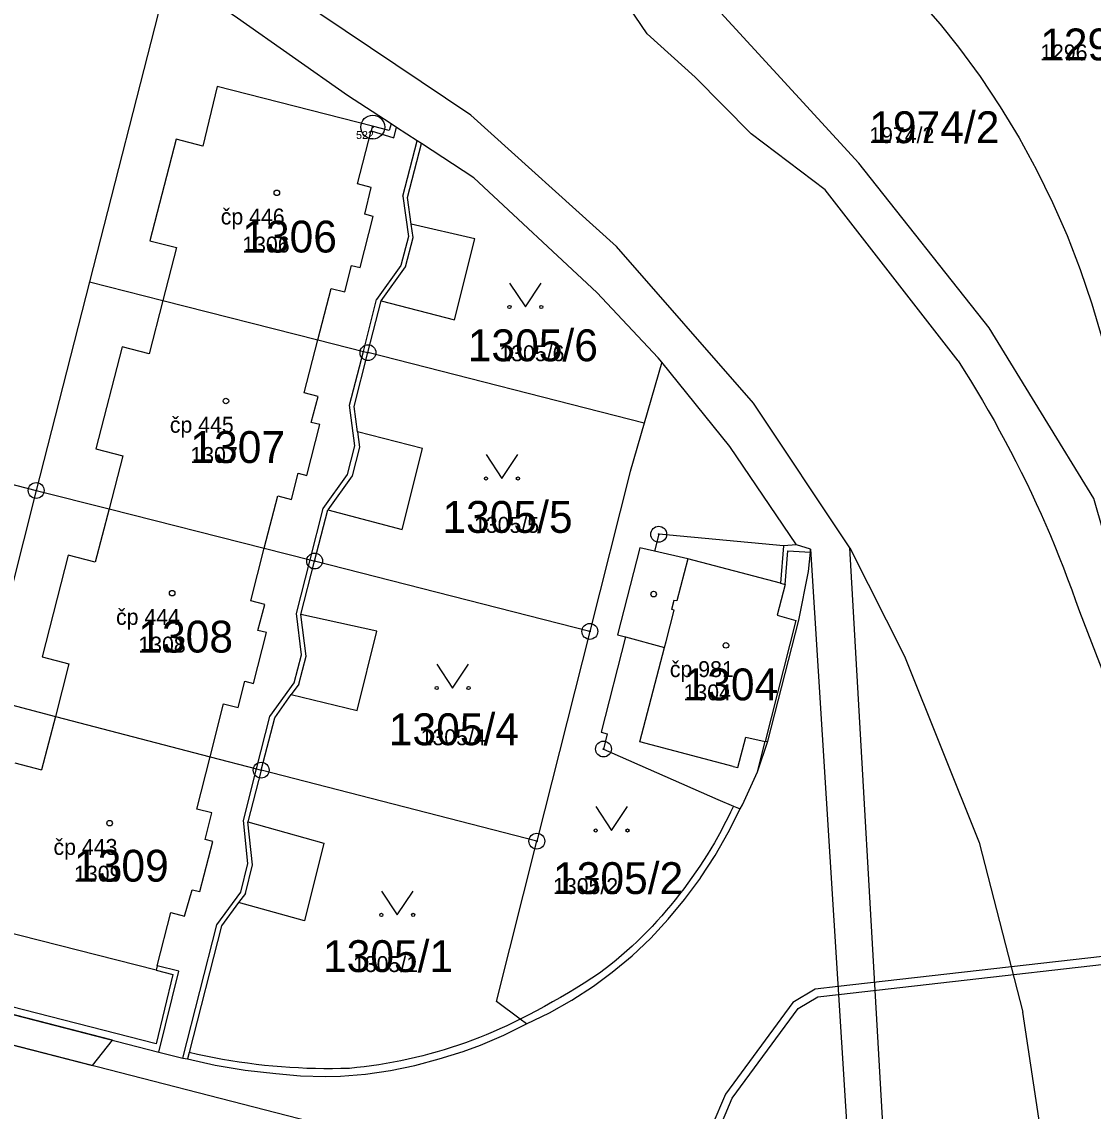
# Model space of a CAD drawing. Extents: x -763628 to -761565, y -976033 to -973833.
# Drawn here: x -762263.5 to -762196.1, y -975446.4 to -975378 of the extents above; entities that cross this region are included whole.
import ezdxf

# ---------------------------------------------------------------- set-up
doc = ezdxf.new("R2010")
doc.units = 0
for name, color, linetype in [('KN_cisla parcel 1000', 7, 'Continuous'), ('KN_cisla parcel 500', 7, 'Continuous'), ('KN_cisla popisna 500', 7, 'Continuous'), ('KN_hranice parcel', 7, 'Continuous'), ('KN_vecna bremena', 7, 'Continuous'), ('KN_vnitrni kresba parcel', 7, 'Continuous'), ('KN_znacky bodu BP', 7, 'Continuous'), ('KN_znacky budov', 7, 'Continuous'), ('KN_znacky kultur', 7, 'Continuous')]:
    doc.layers.add(name, color=color, linetype=linetype)

msp = doc.modelspace()

# ---------------------------------------------------------------- linework, layer by layer
at = {"layer": 'KN_hranice parcel'}
for p, q in [((-762259.22, -975394.29), (-762262.57, -975407.4)), ((-762224.37, -975403.18), (-762241.72, -975398.74)), ((-762223.26, -975399.34), (-762224.37, -975403.18)), ((-762283.84, -975401.95), (-762262.57, -975407.4)), ((-762262.57, -975407.4), (-762265.89, -975420.41)), ((-762213.91, -975411.08), (-762214.79, -975410.81)), ((-762227.78, -975416.25), (-762245.07, -975411.83)), ((-762227.78, -975416.25), (-762231.11, -975429.43)), ((-762231.11, -975429.43), (-762248.43, -975424.97))]:
    msp.add_line(p, q, dxfattribs=at)
for points in [[(-762225.71, -975363.26), (-762223.626, -975364.193), (-762221.585, -975365.216), (-762219.591, -975366.327), (-762217.647, -975367.525), (-762215.758, -975368.807), (-762213.926, -975370.17), (-762212.156, -975371.612), (-762210.451, -975373.131), (-762208.814, -975374.722), (-762207.248, -975376.384), (-762205.756, -975378.112), (-762204.607, -975379.556), (-762203.257, -975381.398), (-762201.989, -975383.296), (-762200.805, -975385.248), (-762199.708, -975387.251), (-762198.699, -975389.299), (-762197.781, -975391.39), (-762196.956, -975393.518), (-762196.224, -975395.681), (-762195.588, -975397.874)], [(-762193.77, -975416.03), (-762194.29, -975414.25), (-762196.11, -975407.9), (-762202.69, -975397.18), (-762210.87, -975386.84), (-762225.62, -975370.76), (-762226.44, -975366.62)], [(-762254.57, -975376.08), (-762254.68, -975376.52), (-762259.22, -975394.29)], [(-762238.36, -975385.61), (-762238.63, -975385.43), (-762239.93, -975384.59), (-762240.26, -975384.37), (-762243, -975382.59), (-762249.92, -975377.74), (-762250.92, -975377.04), (-762254.57, -975376.08)], [(-762241.72, -975398.74), (-762240.89, -975395.49), (-762236.28, -975396.68), (-762235.01, -975391.6), (-762239, -975390.68), (-762239.23, -975389), (-762238.36, -975385.61)], [(-762223.26, -975399.34), (-762223.48, -975399.07), (-762227.34, -975394.96), (-762235.07, -975387.76), (-762238.36, -975385.61)], [(-762259.22, -975394.29), (-762254.61, -975395.46), (-762244.88, -975397.94), (-762242.01, -975398.67), (-762241.72, -975398.74)], [(-762245.07, -975411.83), (-762244.24, -975408.61), (-762239.57, -975409.85), (-762238.3, -975404.77), (-762242.38, -975403.72), (-762242.59, -975402.12), (-762241.72, -975398.74)], [(-762214.79, -975410.81), (-762218.97, -975404.64), (-762223.26, -975399.34)], [(-762224.37, -975403.18), (-762225.25, -975406.21), (-762227.78, -975416.25)], [(-762262.57, -975407.4), (-762257.99, -975408.56), (-762248.24, -975411.03), (-762245.36, -975411.76), (-762245.07, -975411.83)], [(-762214.79, -975410.81), (-762215.61, -975410.87), (-762223.45, -975410.15), (-762223.72, -975411.21), (-762224.63, -975411.01), (-762226.05, -975416.46), (-762225.53, -975416.6), (-762227.07, -975422.58), (-762226.68, -975422.68), (-762226.92, -975423.64), (-762219.74, -975426.81), (-762218.76, -975427.22), (-762218.34, -975427.39)], [(-762218.34, -975427.39), (-762218.18, -975427.14), (-762217.25, -975425.08), (-762216.6, -975423.15), (-762214.65, -975415.55), (-762214.04, -975412.48), (-762213.92, -975411.27), (-762213.91, -975411.08)], [(-762213.91, -975411.08), (-762211.23, -975453.74), (-762211.16, -975455.66), (-762210.96, -975461.11), (-762210.75, -975466.8)], [(-762248.43, -975424.97), (-762247.58, -975421.68), (-762246.54, -975420.22), (-762242.4, -975421.21), (-762241.16, -975416.24), (-762245.93, -975415.19), (-762245.07, -975411.83)], [(-762265.89, -975420.41), (-762261.36, -975421.59), (-762251.64, -975424.13), (-762248.72, -975424.89), (-762248.43, -975424.97)], [(-762248.43, -975424.97), (-762249.26, -975428.21), (-762244.49, -975429.55), (-762245.71, -975434.44), (-762249.85, -975433.29), (-762250.93, -975434.75), (-762252.96, -975442.7), (-762253.06, -975443.11)], [(-762231.76, -975440.91), (-762230.308, -975440.204), (-762228.902, -975439.408), (-762227.548, -975438.528), (-762226.367, -975437.657), (-762225.127, -975436.623), (-762223.952, -975435.515), (-762222.849, -975434.335), (-762221.82, -975433.09), (-762220.825, -975431.748), (-762220.818, -975431.739), (-762219.906, -975430.339), (-762219.079, -975428.888), (-762218.34, -975427.39)], [(-762231.76, -975440.91), (-762232.16, -975440.61), (-762233.65, -975439.49), (-762231.11, -975429.43)], [(-762270.55, -975438.65), (-762254.86, -975442.68), (-762253.36, -975443.06), (-762253.06, -975443.11)], [(-762253.06, -975443.11), (-762251.328, -975443.491), (-762249.431, -975443.81), (-762247.52, -975444.03), (-762245.952, -975444.168), (-762244.379, -975444.206), (-762243.436, -975444.18), (-762241.866, -975444.058), (-762240.308, -975443.837), (-762238.767, -975443.517), (-762237.25, -975443.1), (-762235.729, -975442.64), (-762234.642, -975442.246), (-762233.18, -975441.623), (-762231.76, -975440.91)]]:
    msp.add_lwpolyline(points, dxfattribs=at)
at = {"layer": 'KN_vecna bremena'}
msp.add_lwpolyline([(-762318.38, -975428.27), (-762259.04, -975443.52), (-762257.78, -975441.93), (-762270.55, -975438.65), (-762291.9, -975433.17), (-762292.19, -975433.1), (-762293.64, -975432.73), (-762309.19, -975428.74)], dxfattribs=at)
msp.add_lwpolyline([(-762222.94, -975461.28), (-762220.48, -975449.5), (-762218.83, -975445.58), (-762214.68, -975439.95), (-762213.46, -975439.21), (-762212.15, -975439.06), (-762187.54, -975436.26), (-762187.63, -975435.77), (-762212.18, -975438.56), (-762213.62, -975438.72), (-762215.02, -975439.57), (-762219.26, -975445.33), (-762220.96, -975449.34), (-762223.45, -975461.3), (-762222.83, -975463.59), (-762222.27, -975463.74)], close=True, dxfattribs=at)
at = {"layer": 'KN_vnitrni kresba parcel'}
for p, q in [((-762224.17, -975378.71), (-762227.51, -975373.8)), ((-762235.26, -975383.83), (-762247.22, -975375.79)), ((-762221.15, -975381.43), (-762224.17, -975378.71)), ((-762217.64, -975385), (-762221.15, -975381.43)), ((-762251.2, -975382.03), (-762252.1, -975385.76)), ((-762241.44, -975384.52), (-762251.2, -975382.03)), ((-762226.11, -975392.08), (-762235.26, -975383.83)), ((-762242.37, -975388.14), (-762241.52, -975384.81)), ((-762241.44, -975384.52), (-762241.52, -975384.81)), ((-762241.52, -975384.81), (-762240.1, -975385.25)), ((-762240.38, -975384.79), (-762241.44, -975384.52)), ((-762240.26, -975384.37), (-762240.38, -975384.79)), ((-762240.1, -975385.25), (-762239.93, -975384.59)), ((-762253.78, -975385.32), (-762255.43, -975391.71)), ((-762252.1, -975385.76), (-762253.78, -975385.32)), ((-762239.52, -975388.92), (-762238.63, -975385.43)), ((-762212.99, -975388.51), (-762217.64, -975385)), ((-762241.51, -975388.37), (-762242.37, -975388.14)), ((-762241.92, -975390.05), (-762241.51, -975388.37)), ((-762239.52, -975388.92), (-762239.18, -975391.44)), ((-762204.64, -975399.25), (-762212.99, -975388.51)), ((-762242.21, -975393.4), (-762241.39, -975390.19)), ((-762241.39, -975390.19), (-762241.92, -975390.05)), ((-762238.89, -975391.51), (-762239, -975390.68)), ((-762255.43, -975391.71), (-762253.75, -975392.14)), ((-762239.18, -975391.44), (-762239.66, -975393.27)), ((-762239.36, -975393.35), (-762238.89, -975391.51)), ((-762253.75, -975392.14), (-762254.61, -975395.46)), ((-762217.49, -975401.91), (-762226.11, -975392.08)), ((-762243.18, -975394.93), (-762242.75, -975393.26)), ((-762242.75, -975393.26), (-762242.21, -975393.4)), ((-762239.66, -975393.27), (-762241.18, -975395.41)), ((-762240.89, -975395.49), (-762239.36, -975393.35)), ((-762244.88, -975397.94), (-762244.04, -975394.71)), ((-762244.04, -975394.71), (-762243.18, -975394.93)), ((-762254.61, -975395.46), (-762255.47, -975398.82)), ((-762242.01, -975398.67), (-762241.18, -975395.41)), ((-762245.73, -975401.27), (-762244.88, -975397.94)), ((-762257.16, -975398.38), (-762258.82, -975404.78)), ((-762255.47, -975398.82), (-762257.16, -975398.38)), ((-762242.88, -975402.04), (-762242.01, -975398.67)), ((-762244.86, -975401.49), (-762245.73, -975401.27)), ((-762245.28, -975403.13), (-762244.86, -975401.49)), ((-762242.55, -975404.6), (-762242.88, -975402.04)), ((-762211.43, -975411.01), (-762217.49, -975401.91)), ((-762245.56, -975406.45), (-762244.75, -975403.26)), ((-762244.75, -975403.26), (-762245.28, -975403.13)), ((-762242.38, -975403.72), (-762242.26, -975404.68)), ((-762258.82, -975404.78), (-762257.12, -975405.22)), ((-762243.01, -975406.39), (-762242.55, -975404.6)), ((-762242.26, -975404.68), (-762242.72, -975406.47)), ((-762257.12, -975405.22), (-762257.99, -975408.56)), ((-762246.52, -975407.96), (-762246.1, -975406.31)), ((-762246.1, -975406.31), (-762245.56, -975406.45)), ((-762244.54, -975408.53), (-762243.01, -975406.39)), ((-762242.72, -975406.47), (-762244.24, -975408.61)), ((-762248.24, -975411.03), (-762247.39, -975407.74)), ((-762247.39, -975407.74), (-762246.52, -975407.96)), ((-762257.99, -975408.56), (-762258.86, -975411.91)), ((-762245.36, -975411.76), (-762244.54, -975408.53)), ((-762215.61, -975410.87), (-762215.79, -975413.22)), ((-762260.55, -975411.47), (-762262.2, -975417.84)), ((-762258.86, -975411.91), (-762260.55, -975411.47)), ((-762249.09, -975414.33), (-762248.24, -975411.03)), ((-762221.62, -975411.69), (-762223.72, -975411.21)), ((-762215.5, -975413.3), (-762215.34, -975411.2)), ((-762215.34, -975411.2), (-762213.92, -975411.27)), ((-762209, -975453.44), (-762211.43, -975411.01)), ((-762211.43, -975411.01), (-762208, -975417.8)), ((-762246.22, -975415.12), (-762245.36, -975411.76)), ((-762221.62, -975411.69), (-762222.32, -975414.34)), ((-762215.79, -975413.22), (-762221.62, -975411.69)), ((-762215.5, -975413.3), (-762216, -975415.24)), ((-762215.79, -975413.22), (-762215.5, -975413.3)), ((-762248.21, -975414.56), (-762249.09, -975414.33)), ((-762222.49, -975414.3), (-762222.64, -975414.88)), ((-762222.32, -975414.34), (-762222.49, -975414.3)), ((-762248.64, -975416.19), (-762248.21, -975414.56)), ((-762222.98, -975416.89), (-762222.47, -975414.92)), ((-762222.47, -975414.92), (-762222.64, -975414.88)), ((-762197.01, -975415.01), (-762193.8, -975423.3)), ((-762245.9, -975417.72), (-762246.22, -975415.12)), ((-762245.61, -975417.8), (-762245.93, -975415.19)), ((-762214.83, -975415.57), (-762216.76, -975423.16)), ((-762216, -975415.24), (-762214.83, -975415.57)), ((-762248.92, -975419.52), (-762248.1, -975416.33)), ((-762248.1, -975416.33), (-762248.64, -975416.19)), ((-762225.53, -975416.6), (-762223.08, -975417.26)), ((-762223.08, -975417.26), (-762222.98, -975416.89)), ((-762246.35, -975419.48), (-762245.9, -975417.72)), ((-762246.06, -975419.56), (-762245.61, -975417.8)), ((-762224.64, -975423.19), (-762223.08, -975417.26)), ((-762208, -975417.8), (-762203.31, -975429.52)), ((-762262.2, -975417.84), (-762260.51, -975418.28)), ((-762260.51, -975418.28), (-762261.36, -975421.59)), ((-762249.88, -975421.04), (-762249.45, -975419.38)), ((-762249.45, -975419.38), (-762248.92, -975419.52)), ((-762247.88, -975421.6), (-762246.35, -975419.48)), ((-762246.06, -975419.56), (-762246.54, -975420.22)), ((-762251.64, -975424.13), (-762250.79, -975420.8)), ((-762250.79, -975420.8), (-762249.88, -975421.04)), ((-762261.36, -975421.59), (-762262.23, -975424.94)), ((-762248.72, -975424.89), (-762247.88, -975421.6)), ((-762218.77, -975424.74), (-762224.64, -975423.19)), ((-762218.47, -975424.81), (-762217.97, -975422.89)), ((-762217.97, -975422.89), (-762216.76, -975423.16)), ((-762217.25, -975425.08), (-762216.76, -975423.16)), ((-762216.76, -975423.16), (-762216.6, -975423.15)), ((-762263.92, -975424.5), (-762262.23, -975424.94)), ((-762252.48, -975427.41), (-762251.64, -975424.13)), ((-762249.55, -975428.14), (-762248.72, -975424.89)), ((-762218.77, -975424.74), (-762218.47, -975424.81)), ((-762251.53, -975427.65), (-762252.48, -975427.41)), ((-762251.95, -975429.32), (-762251.53, -975427.65)), ((-762211.66, -975455.7), (-762318.38, -975428.27)), ((-762249.26, -975430.84), (-762249.55, -975428.14)), ((-762248.97, -975430.92), (-762249.26, -975428.21)), ((-762252.28, -975432.6), (-762251.47, -975429.44)), ((-762251.47, -975429.44), (-762251.95, -975429.32)), ((-762203.31, -975429.52), (-762200.56, -975440.18)), ((-762249.72, -975432.63), (-762249.26, -975430.84)), ((-762249.42, -975432.71), (-762248.97, -975430.92)), ((-762253.24, -975434.13), (-762252.76, -975432.48)), ((-762252.76, -975432.48), (-762252.28, -975432.6)), ((-762251.22, -975434.68), (-762249.72, -975432.63)), ((-762249.42, -975432.71), (-762249.85, -975433.29)), ((-762254.96, -975437.25), (-762254.11, -975433.9)), ((-762254.11, -975433.9), (-762253.24, -975434.13)), ((-762253.36, -975443.06), (-762251.22, -975434.68)), ((-762255.04, -975437.54), (-762264.83, -975435.03)), ((-762254.96, -975437.25), (-762255.04, -975437.54)), ((-762255.04, -975437.54), (-762253.98, -975437.81)), ((-762253.6, -975437.6), (-762254.96, -975437.25)), ((-762254.86, -975442.68), (-762253.6, -975437.6)), ((-762255.04, -975442.16), (-762270.44, -975438.21)), ((-762253.98, -975437.81), (-762255.04, -975442.16)), ((-762198.91, -975451.2), (-762200.56, -975440.18))]:
    msp.add_line(p, q, dxfattribs=at)
for points in [[(-762204.64, -975399.25), (-762204.247, -975399.867), (-762203.861, -975400.488), (-762203.481, -975401.113), (-762203.107, -975401.741), (-762202.74, -975402.374), (-762202.379, -975403.01), (-762202.024, -975403.649), (-762201.676, -975404.293), (-762201.334, -975404.939), (-762200.999, -975405.589), (-762200.67, -975406.243), (-762200.348, -975406.899), (-762200.033, -975407.559), (-762199.724, -975408.222), (-762199.422, -975408.888), (-762199.127, -975409.557), (-762198.838, -975410.229), (-762198.557, -975410.904), (-762198.282, -975411.582), (-762198.014, -975412.262), (-762197.752, -975412.945), (-762197.498, -975413.631), (-762197.25, -975414.319), (-762197.01, -975415.01)], [(-762218.76, -975427.22), (-762218.943, -975427.613), (-762219.132, -975428.004), (-762219.327, -975428.391), (-762219.529, -975428.775), (-762219.736, -975429.156), (-762219.95, -975429.533), (-762220.17, -975429.907), (-762220.396, -975430.277), (-762220.628, -975430.643), (-762220.866, -975431.006), (-762221.109, -975431.365), (-762221.358, -975431.72), (-762221.613, -975432.071), (-762221.874, -975432.418), (-762222.14, -975432.76)], [(-762222.14, -975432.76), (-762222.412, -975433.11), (-762222.69, -975433.455), (-762222.974, -975433.794), (-762223.264, -975434.129), (-762223.56, -975434.459), (-762223.861, -975434.784), (-762224.168, -975435.103), (-762224.481, -975435.417), (-762224.799, -975435.725), (-762225.122, -975436.027), (-762225.451, -975436.324), (-762225.785, -975436.615), (-762226.124, -975436.901), (-762226.468, -975437.18), (-762226.817, -975437.453), (-762227.17, -975437.72)], [(-762227.17, -975437.72), (-762227.652, -975438.037), (-762228.138, -975438.348), (-762228.629, -975438.652), (-762229.122, -975438.951), (-762229.62, -975439.243), (-762230.121, -975439.529), (-762230.626, -975439.809), (-762231.134, -975440.082), (-762231.645, -975440.349), (-762232.16, -975440.61)], [(-762232.16, -975440.61), (-762232.579, -975440.819), (-762233.001, -975441.021), (-762233.426, -975441.217), (-762233.854, -975441.406), (-762234.286, -975441.588), (-762234.72, -975441.763), (-762235.156, -975441.932), (-762235.596, -975442.093), (-762236.038, -975442.247), (-762236.482, -975442.394), (-762236.929, -975442.535), (-762237.377, -975442.668), (-762237.828, -975442.794), (-762238.281, -975442.912), (-762238.735, -975443.024), (-762239.192, -975443.128), (-762239.65, -975443.225), (-762240.109, -975443.315), (-762240.57, -975443.398), (-762241.032, -975443.473), (-762241.495, -975443.541), (-762241.959, -975443.601), (-762242.424, -975443.654), (-762242.89, -975443.7)], [(-762242.89, -975443.7), (-762243.424, -975443.715), (-762243.958, -975443.722), (-762244.492, -975443.722), (-762245.026, -975443.715), (-762245.56, -975443.7), (-762246.094, -975443.677), (-762246.628, -975443.647), (-762247.16, -975443.609), (-762247.693, -975443.564), (-762248.224, -975443.511), (-762248.755, -975443.451), (-762249.285, -975443.383), (-762249.814, -975443.308), (-762250.342, -975443.225), (-762250.868, -975443.135), (-762251.393, -975443.037), (-762251.917, -975442.932), (-762252.439, -975442.82), (-762252.96, -975442.7)]]:
    msp.add_lwpolyline(points, dxfattribs=at)
at = {"layer": 'KN_znacky bodu BP'}
for centre, radius in [((-762241.42, -975384.57), 0.75), ((-762241.42, -975384.57), 0.03), ((-762241.72, -975398.74), 0.5), ((-762241.72, -975398.74), 0.0303), ((-762262.57, -975407.4), 0.5), ((-762262.57, -975407.4), 0.0303), ((-762223.45, -975410.15), 0.5), ((-762223.45, -975410.15), 0.0303), ((-762245.07, -975411.83), 0.5), ((-762245.07, -975411.83), 0.0303), ((-762227.78, -975416.25), 0.5), ((-762227.78, -975416.25), 0.0303), ((-762226.92, -975423.64), 0.5), ((-762226.92, -975423.64), 0.0303), ((-762248.43, -975424.97), 0.5), ((-762248.43, -975424.97), 0.0303), ((-762231.11, -975429.43), 0.5), ((-762231.11, -975429.43), 0.0303)]:
    msp.add_circle(centre, radius, dxfattribs=at)
at = {"layer": 'KN_znacky budov'}
for centre in [(-762247.447, -975388.699), (-762250.647, -975401.779), (-762254.027, -975413.849), (-762223.767, -975413.909), (-762219.227, -975417.129), (-762257.957, -975428.299)]:
    msp.add_circle(centre, 0.175, dxfattribs=at)
at = {"layer": 'KN_znacky kultur'}
for points in [[(-762232.83, -975394.369), (-762231.83, -975395.87), (-762230.83, -975394.369)], [(-762234.3, -975405.149), (-762233.3, -975406.65), (-762232.3, -975405.149)], [(-762237.4, -975418.309), (-762236.4, -975419.81), (-762235.4, -975418.309)], [(-762227.41, -975427.259), (-762226.41, -975428.76), (-762225.41, -975427.259)], [(-762240.88, -975432.559), (-762239.88, -975434.06), (-762238.88, -975432.559)]]:
    msp.add_lwpolyline(points, dxfattribs=at)
for centre in [(-762232.83, -975395.869), (-762230.83, -975395.869), (-762234.3, -975406.649), (-762232.3, -975406.649), (-762237.4, -975419.809), (-762235.4, -975419.809), (-762227.41, -975428.759), (-762225.41, -975428.759), (-762240.88, -975434.059), (-762238.88, -975434.059)]:
    msp.add_circle(centre, 0.1, dxfattribs=at)

# ---------------------------------------------------------------- texts
at = {"layer": 'KN_cisla parcel 1000'}
for s, p in [('1296', (-762199.48, -975380.38)), ('1974/2', (-762210.22, -975385.58)), ('1306', (-762249.62, -975392.45)), ('1305/6', (-762235.449, -975399.28)), ('1307', (-762252.88, -975405.67)), ('1305/5', (-762237.042, -975410.06)), ('1308', (-762256.15, -975417.58)), ('1304', (-762221.89, -975420.58)), ('1305/4', (-762240.412, -975423.4)), ('1309', (-762260.19, -975431.97)), ('1305/2', (-762230.09, -975432.75)), ('1305/1', (-762244.547, -975437.65))]:
    msp.add_text(s, height=2, dxfattribs=at).set_placement(p)
at = {"layer": 'KN_cisla parcel 500'}
for s, p in [('1296', (-762199.48, -975380.38)), ('1974/2', (-762210.22, -975385.58)), ('1306', (-762249.62, -975392.45)), ('1305/6', (-762233.465, -975399.28)), ('1307', (-762252.88, -975405.67)), ('1305/5', (-762235.058, -975410.06)), ('1308', (-762256.15, -975417.58)), ('1304', (-762221.89, -975420.58)), ('1305/4', (-762238.412, -975423.4)), ('1309', (-762260.19, -975431.97)), ('1305/2', (-762230.09, -975432.75)), ('1305/1', (-762242.663, -975437.65))]:
    msp.add_text(s, height=1, dxfattribs=at).set_placement(p)
at = {"layer": 'KN_cisla popisna 500'}
for s, p in [('čp 446', (-762250.971, -975390.691)), ('čp 445', (-762254.171, -975403.771)), ('čp 444', (-762257.551, -975415.841)), ('čp 981', (-762222.751, -975419.121)), ('čp 443', (-762261.481, -975430.291))]:
    msp.add_text(s, height=1, dxfattribs=at).set_placement(p)
at = {"layer": 'KN_znacky bodu BP'}
msp.add_text('522', height=0.5, dxfattribs=at).set_placement((-762242.469, -975385.32))

doc.saveas('drawing.dxf')
